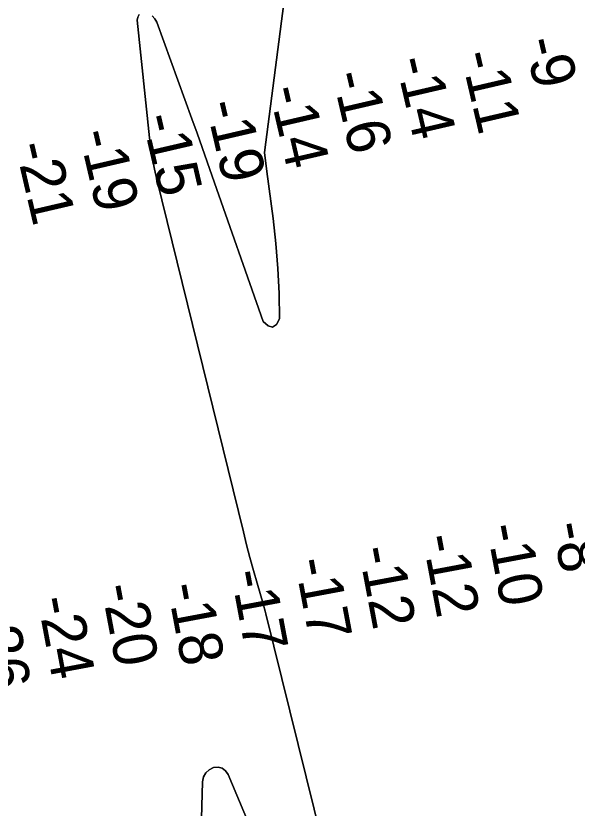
# Model space of a CAD drawing. Extents: x 3161665 to 3199565, y 885729 to 911164.
# Drawn here: x 3176953 to 3177817, y 894760 to 895980 of the extents above; entities that cross this region are included whole.
import ezdxf

# ---------------------------------------------------------------- set-up
doc = ezdxf.new("R2010")
doc.units = 0
for name, color, linetype in [('V-RIVR-RANG', 7, 'Continuous'), ('V-TOPO-DPTH', 7, 'Continuous'), ('V-TOPO-MINR', 7, 'Continuous')]:
    doc.layers.add(name, color=color, linetype=linetype)

msp = doc.modelspace()

# ---------------------------------------------------------------- linework, layer by layer
at = {"layer": 'V-TOPO-DPTH'}
for points in [[(3177162.9, 895980), (3177166.9, 895975.5), (3177170, 895970.1), (3177223.8, 895821.4), (3177231.8, 895799.4), (3177239.7, 895777.3), (3177247.5, 895755.3), (3177255.2, 895733.2), (3177333.6, 895509.1), (3177341.2, 895502.6), (3177348.1, 895500.5), (3177353.9, 895504.8), (3177359, 895513.4), (3177358.2, 895552.1), (3177356.4, 895590.7), (3177353.1, 895629.2), (3177348.8, 895667.6), (3177339.4, 895740.3), (3177335.7, 895769.4), (3177426.3, 896471.6)], [(3177426.3, 896471.6), (3177335.7, 895769.4), (3177339.4, 895740.3), (3177348.8, 895667.6), (3177353.1, 895629.2), (3177356.4, 895590.7), (3177358.2, 895552.1), (3177359, 895513.4), (3177353.9, 895504.8), (3177348.1, 895500.5), (3177341.2, 895502.6), (3177333.6, 895509.1), (3177255.2, 895733.2), (3177247.5, 895755.3), (3177239.7, 895777.3), (3177231.8, 895799.4), (3177223.8, 895821.4), (3177170, 895970.1), (3177166.9, 895975.5), (3177162.9, 895980)], [(3177424.3, 894708.2), (3177337.9, 895059.2), (3177336.9, 895063), (3177335.9, 895066.9), (3177334.8, 895070.7), (3177333.7, 895074.5), (3177324.4, 895106.1), (3177318.8, 895125.8), (3177313.3, 895145.5), (3177308.1, 895165.3), (3177303.1, 895185.1), (3177170, 895727.8), (3177166.5, 895743.7), (3177163.3, 895759.7), (3177160.8, 895775.9), (3177158.8, 895792.1), (3177139.6, 895973), (3177140.6, 895978), (3177142.8, 895981.8)], [(3177142.8, 895981.8), (3177140.6, 895978), (3177139.6, 895973), (3177158.8, 895792.1), (3177160.8, 895775.9), (3177163.3, 895759.7), (3177166.5, 895743.7), (3177170, 895727.8), (3177303.1, 895185.1), (3177308.1, 895165.3), (3177313.3, 895145.5), (3177318.8, 895125.8), (3177324.4, 895106.1), (3177333.7, 895074.5), (3177334.8, 895070.7), (3177335.9, 895066.9), (3177336.9, 895063), (3177337.9, 895059.2), (3177424.3, 894708.2)], [(3177234.4, 894594.1), (3177240.3, 894800.4), (3177242, 894807.8), (3177245.2, 894814), (3177250.4, 894818.7), (3177257, 894822.3), (3177264.1, 894822.7), (3177270.4, 894821.4), (3177275.4, 894817.4), (3177279.7, 894811.7), (3177446.9, 894412.5)], [(3177446.9, 894412.5), (3177279.7, 894811.7), (3177275.4, 894817.4), (3177270.4, 894821.4), (3177264.1, 894822.7), (3177257, 894822.3), (3177250.4, 894818.7), (3177245.2, 894814), (3177242, 894807.8), (3177240.3, 894800.4), (3177234.4, 894594.1)]]:
    msp.add_lwpolyline(points, dxfattribs=at)
at = {"layer": 'V-TOPO-MINR'}
for points in [[(3177426.3, 896471.6), (3177335.7, 895769.4), (3177339.4, 895740.3), (3177348.8, 895667.6), (3177353.1, 895629.2), (3177356.4, 895590.7), (3177358.2, 895552.1), (3177359, 895513.4), (3177353.9, 895504.8), (3177348.1, 895500.5), (3177341.2, 895502.6), (3177333.6, 895509.1), (3177255.2, 895733.2), (3177247.5, 895755.3), (3177239.7, 895777.3), (3177231.8, 895799.4), (3177223.8, 895821.4), (3177170, 895970.1), (3177166.9, 895975.5), (3177162.9, 895980)], [(3177142.8, 895981.8), (3177140.6, 895978), (3177139.6, 895973), (3177158.8, 895792.1), (3177160.8, 895775.9), (3177163.3, 895759.7), (3177166.5, 895743.7), (3177170, 895727.8), (3177303.1, 895185.1), (3177308.1, 895165.3), (3177313.3, 895145.5), (3177318.8, 895125.8), (3177324.4, 895106.1), (3177333.7, 895074.5), (3177334.8, 895070.7), (3177335.9, 895066.9), (3177336.9, 895063), (3177337.9, 895059.2), (3177424.3, 894708.2)], [(3177446.9, 894412.5), (3177279.7, 894811.7), (3177275.4, 894817.4), (3177270.4, 894821.4), (3177264.1, 894822.7), (3177257, 894822.3), (3177250.4, 894818.7), (3177245.2, 894814), (3177242, 894807.8), (3177240.3, 894800.4), (3177234.4, 894594.1)]]:
    msp.add_lwpolyline(points, dxfattribs=at)

# ---------------------------------------------------------------- texts
at = {"layer": 'V-RIVR-RANG'}
for s, rotation, p in [('-9', 283.0792, (3177735.2, 895941.4)), ('-11', 283.0792, (3177637.4, 895920.6)), ('-14', 283.0792, (3177536.8, 895911.6)), ('-16', 283.0792, (3177439.3, 895889.4)), ('-14', 283.0792, (3177341.9, 895866.8)), ('-19', 283.0792, (3177244.4, 895844.4)), ('-15', 283.0792, (3177146.5, 895823.8)), ('-19', 283.0792, (3177049.5, 895799.6)), ('-21', 283.0792, (3176951.3, 895780.3)), ('-10', 280.6283, (3177677, 895193.8)), ('-8', 280.6283, (3177778.2, 895196.7)), ('-12', 280.6283, (3177578.3, 895177.4)), ('-12', 280.6283, (3177480, 895159.2)), ('-17', 280.6283, (3177381.6, 895141)), ('-17', 280.6283, (3177283.3, 895122.8)), ('-20', 280.6283, (3177083.9, 895101.2)), ('-18', 280.6283, (3177185.4, 895102.5)), ('-24', 280.6283, (3176985.7, 895081.9)), ('-26', 280.6283, (3176887.4, 895064))]:
    msp.add_text(s, height=67, rotation=rotation, dxfattribs=at).set_placement(p)

doc.saveas('drawing.dxf')
